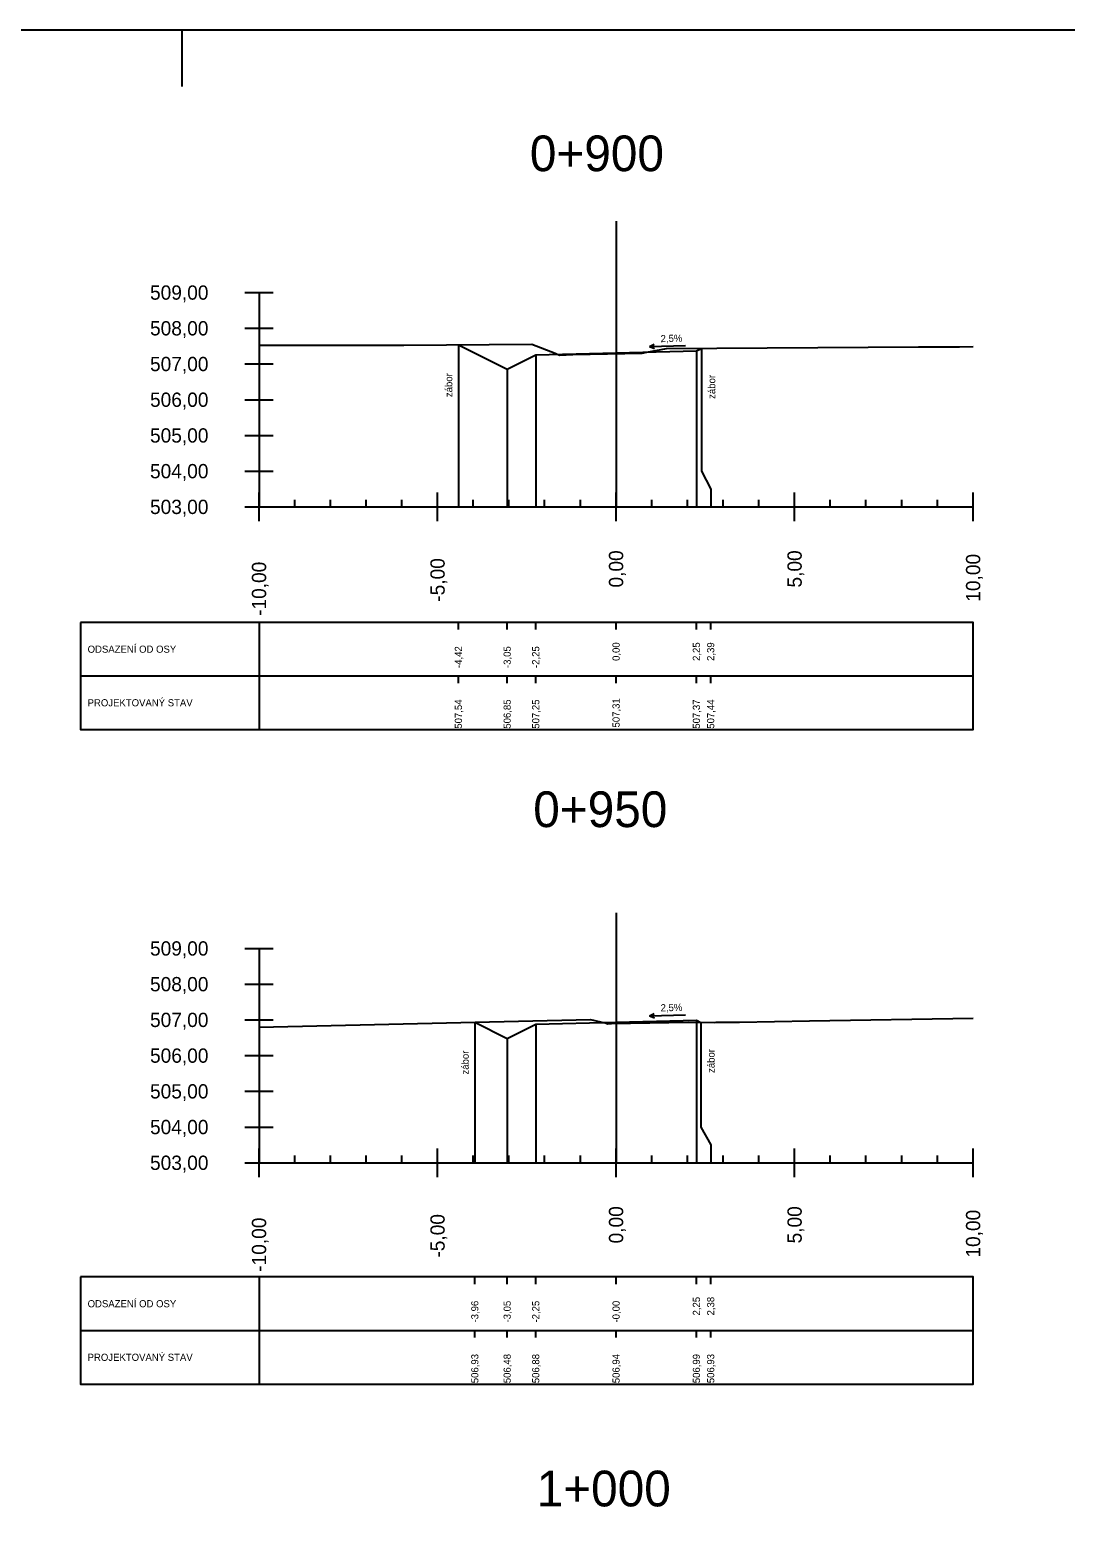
# Model space of a CAD drawing. Extents: x -631407 to -631215, y -1089700 to -1088598.
# Drawn here: x -631345.64 to -631316.63, y -1088807.44 to -1088765.23 of the extents above; entities that cross this region are included whole.
import ezdxf

# ---------------------------------------------------------------- set-up
doc = ezdxf.new("R2010")
doc.units = 0
for name, color, linetype in [('08_LEGENDA_HV', 7, 'Continuous'), ('59', 7, 'Continuous'), ('DTM-Breaklines', 7, 'Continuous'), ('NIVELETA_VYSKY', 7, 'Continuous'), ('REZ_BODY', 7, 'Continuous'), ('REZ_ODSTUPY', 7, 'Continuous'), ('REZ_POPIS', 7, 'Continuous'), ('REZ_RAMY', 7, 'Continuous'), ('REZ_STANICENI', 7, 'Continuous'), ('REZ_SVISLE', 7, 'Continuous'), ('REZ_TENKA', 7, 'Continuous'), ('REZ_TLUSTA', 7, 'Continuous'), ('TABULKA_POPIS', 7, 'Continuous'), ('TEREN', 7, 'Continuous'), ('zábor', 7, 'Continuous')]:
    doc.layers.add(name, color=color, linetype=linetype)

msp = doc.modelspace()

# ---------------------------------------------------------------- linework, layer by layer
at = {"layer": '08_LEGENDA_HV'}
msp.add_lwpolyline([(-631215.384, -1088943.435), (-631215.384, -1088765.235), (-631407.014, -1088765.235), (-631407.014, -1088943.435)], close=True, dxfattribs=at)
at = {"layer": '59'}
for p, q in [((-631339.63, -1088772.581), (-631338.83, -1088772.581)), ((-631339.23, -1088772.581), (-631339.23, -1088778.581)), ((-631339.63, -1088773.581), (-631338.83, -1088773.581)), ((-631339.63, -1088774.581), (-631338.83, -1088774.581)), ((-631339.63, -1088775.581), (-631338.83, -1088775.581)), ((-631339.63, -1088776.581), (-631338.83, -1088776.581)), ((-631339.63, -1088777.581), (-631338.83, -1088777.581)), ((-631339.63, -1088778.581), (-631338.83, -1088778.581)), ((-631339.63, -1088790.943), (-631338.83, -1088790.943)), ((-631339.23, -1088790.943), (-631339.23, -1088796.943)), ((-631339.63, -1088791.943), (-631338.83, -1088791.943)), ((-631339.63, -1088792.943), (-631338.83, -1088792.943)), ((-631339.63, -1088793.943), (-631338.83, -1088793.943)), ((-631339.63, -1088794.943), (-631338.83, -1088794.943)), ((-631339.63, -1088795.943), (-631338.83, -1088795.943)), ((-631339.63, -1088796.943), (-631338.83, -1088796.943))]:
    msp.add_line(p, q, dxfattribs=at)
at = {"layer": 'DTM-Breaklines'}
msp.add_line((-631341.384, -1088766.815), (-631341.384, -1088765.235), dxfattribs=at)
at = {"layer": 'REZ_RAMY'}
for p, q in [((-631344.23, -1088781.815), (-631344.23, -1088784.815)), ((-631339.23, -1088781.815), (-631339.23, -1088784.815)), ((-631333.646, -1088782.015), (-631333.646, -1088781.815)), ((-631332.28, -1088782.015), (-631332.28, -1088781.815)), ((-631331.48, -1088782.015), (-631331.48, -1088781.815)), ((-631329.23, -1088782.015), (-631329.23, -1088781.815)), ((-631326.98, -1088782.015), (-631326.98, -1088781.815)), ((-631326.58, -1088782.015), (-631326.58, -1088781.815)), ((-631344.23, -1088783.315), (-631319.23, -1088783.315)), ((-631333.646, -1088783.515), (-631333.646, -1088783.315)), ((-631332.28, -1088783.515), (-631332.28, -1088783.315)), ((-631331.48, -1088783.515), (-631331.48, -1088783.315)), ((-631329.23, -1088783.515), (-631329.23, -1088783.315)), ((-631326.98, -1088783.515), (-631326.98, -1088783.315)), ((-631326.58, -1088783.515), (-631326.58, -1088783.315)), ((-631344.23, -1088800.139), (-631344.23, -1088803.139)), ((-631339.23, -1088800.139), (-631339.23, -1088803.139)), ((-631333.186, -1088800.339), (-631333.186, -1088800.139)), ((-631332.28, -1088800.339), (-631332.28, -1088800.139)), ((-631331.48, -1088800.339), (-631331.48, -1088800.139)), ((-631329.23, -1088800.339), (-631329.23, -1088800.139)), ((-631326.98, -1088800.339), (-631326.98, -1088800.139)), ((-631326.58, -1088800.339), (-631326.58, -1088800.139)), ((-631344.23, -1088801.639), (-631319.23, -1088801.639)), ((-631333.186, -1088801.839), (-631333.186, -1088801.639)), ((-631332.28, -1088801.839), (-631332.28, -1088801.639)), ((-631331.48, -1088801.839), (-631331.48, -1088801.639)), ((-631329.23, -1088801.839), (-631329.23, -1088801.639)), ((-631326.98, -1088801.839), (-631326.98, -1088801.639)), ((-631326.58, -1088801.839), (-631326.58, -1088801.639))]:
    msp.add_line(p, q, dxfattribs=at)
for points in [[(-631344.23, -1088781.815), (-631344.23, -1088784.815), (-631319.23, -1088784.815), (-631319.23, -1088781.815)], [(-631344.23, -1088800.139), (-631344.23, -1088803.139), (-631319.23, -1088803.139), (-631319.23, -1088800.139)]]:
    msp.add_lwpolyline(points, close=True, dxfattribs=at)
at = {"layer": 'REZ_SVISLE'}
for points in [[(-631333.646, -1088774.044), (-631333.646, -1088777.581), (-631333.646, -1088778.081), (-631333.646, -1088778.581)], [(-631326.98, -1088774.215), (-631326.98, -1088777.581), (-631326.98, -1088778.081), (-631326.98, -1088778.581)], [(-631326.835, -1088774.143), (-631326.835, -1088777.581), (-631326.58, -1088778.081), (-631326.58, -1088778.581)], [(-631331.48, -1088774.327), (-631331.48, -1088777.581), (-631331.48, -1088778.081), (-631331.48, -1088778.581)], [(-631329.23, -1088774.271), (-631329.23, -1088777.581), (-631329.23, -1088778.081), (-631329.23, -1088778.581)], [(-631332.28, -1088774.727), (-631332.28, -1088777.581), (-631332.28, -1088778.081), (-631332.28, -1088778.581)], [(-631333.186, -1088793.009), (-631333.186, -1088795.943), (-631333.186, -1088796.443), (-631333.186, -1088796.943)], [(-631331.48, -1088793.063), (-631331.48, -1088795.943), (-631331.48, -1088796.443), (-631331.48, -1088796.943)], [(-631329.23, -1088793.006), (-631329.23, -1088795.943), (-631329.23, -1088796.443), (-631329.23, -1088796.943)], [(-631326.98, -1088792.95), (-631326.98, -1088795.943), (-631326.98, -1088796.443), (-631326.98, -1088796.943)], [(-631326.854, -1088793.013), (-631326.854, -1088795.943), (-631326.58, -1088796.443), (-631326.58, -1088796.943)], [(-631332.28, -1088793.463), (-631332.28, -1088795.943), (-631332.28, -1088796.443), (-631332.28, -1088796.943)]]:
    msp.add_lwpolyline(points, dxfattribs=at)
at = {"layer": 'REZ_TENKA'}
for p, q in [((-631338.23, -1088778.581), (-631338.23, -1088778.381)), ((-631337.23, -1088778.581), (-631337.23, -1088778.381)), ((-631336.23, -1088778.581), (-631336.23, -1088778.381)), ((-631335.23, -1088778.581), (-631335.23, -1088778.381)), ((-631333.23, -1088778.581), (-631333.23, -1088778.381)), ((-631332.23, -1088778.581), (-631332.23, -1088778.381)), ((-631331.23, -1088778.581), (-631331.23, -1088778.381)), ((-631330.23, -1088778.581), (-631330.23, -1088778.381)), ((-631328.23, -1088778.581), (-631328.23, -1088778.381)), ((-631327.23, -1088778.581), (-631327.23, -1088778.381)), ((-631326.23, -1088778.581), (-631326.23, -1088778.381)), ((-631325.23, -1088778.581), (-631325.23, -1088778.381)), ((-631323.23, -1088778.581), (-631323.23, -1088778.381)), ((-631322.23, -1088778.581), (-631322.23, -1088778.381)), ((-631321.23, -1088778.581), (-631321.23, -1088778.381)), ((-631320.23, -1088778.581), (-631320.23, -1088778.381)), ((-631338.23, -1088796.943), (-631338.23, -1088796.743)), ((-631337.23, -1088796.943), (-631337.23, -1088796.743)), ((-631336.23, -1088796.943), (-631336.23, -1088796.743)), ((-631335.23, -1088796.943), (-631335.23, -1088796.743)), ((-631333.23, -1088796.943), (-631333.23, -1088796.743)), ((-631332.23, -1088796.943), (-631332.23, -1088796.743)), ((-631331.23, -1088796.943), (-631331.23, -1088796.743)), ((-631330.23, -1088796.943), (-631330.23, -1088796.743)), ((-631328.23, -1088796.943), (-631328.23, -1088796.743)), ((-631327.23, -1088796.943), (-631327.23, -1088796.743)), ((-631326.23, -1088796.943), (-631326.23, -1088796.743)), ((-631325.23, -1088796.943), (-631325.23, -1088796.743)), ((-631323.23, -1088796.943), (-631323.23, -1088796.743)), ((-631322.23, -1088796.943), (-631322.23, -1088796.743)), ((-631321.23, -1088796.943), (-631321.23, -1088796.743)), ((-631320.23, -1088796.943), (-631320.23, -1088796.743))]:
    msp.add_line(p, q, dxfattribs=at)
at = {"layer": 'REZ_TLUSTA'}
for p, q in [((-631329.23, -1088770.581), (-631329.23, -1088778.581)), ((-631339.23, -1088778.981), (-631339.23, -1088778.181)), ((-631334.23, -1088778.981), (-631334.23, -1088778.181)), ((-631329.23, -1088778.981), (-631329.23, -1088778.181)), ((-631324.23, -1088778.981), (-631324.23, -1088778.181)), ((-631319.23, -1088778.981), (-631319.23, -1088778.181)), ((-631339.23, -1088778.581), (-631319.23, -1088778.581)), ((-631329.23, -1088789.943), (-631329.23, -1088796.943)), ((-631339.23, -1088797.343), (-631339.23, -1088796.543)), ((-631334.23, -1088797.343), (-631334.23, -1088796.543)), ((-631329.23, -1088797.343), (-631329.23, -1088796.543)), ((-631324.23, -1088797.343), (-631324.23, -1088796.543)), ((-631319.23, -1088797.343), (-631319.23, -1088796.543)), ((-631339.23, -1088796.943), (-631319.23, -1088796.943))]:
    msp.add_line(p, q, dxfattribs=at)
at = {"layer": 'TEREN'}
for points in [[(-631339.23, -1088774.057), (-631335.173, -1088774.058), (-631331.587, -1088774.026), (-631330.936, -1088774.282), (-631330.814, -1088774.33), (-631330.443, -1088774.317), (-631328.498, -1088774.278), (-631328.368, -1088774.254), (-631327.813, -1088774.149), (-631320.761, -1088774.101), (-631319.608, -1088774.098), (-631319.23, -1088774.093)], [(-631333.646, -1088774.044), (-631332.28, -1088774.727), (-631331.48, -1088774.327), (-631329.23, -1088774.271), (-631326.98, -1088774.215), (-631326.835, -1088774.143)], [(-631339.23, -1088793.149), (-631329.945, -1088792.934), (-631329.504, -1088793.034), (-631329.467, -1088793.049), (-631329.355, -1088793.044), (-631327.214, -1088793.011), (-631326.463, -1088793.015), (-631326.422, -1088793.008), (-631325.772, -1088793.007), (-631323.81, -1088792.965), (-631319.23, -1088792.892)], [(-631333.186, -1088793.009), (-631332.28, -1088793.463), (-631331.48, -1088793.063), (-631329.23, -1088793.006), (-631326.98, -1088792.95), (-631326.854, -1088793.013)]]:
    msp.add_lwpolyline(points, dxfattribs=at)
at = {"layer": 'zábor'}
for p, q in [((-631328.297, -1088774.092), (-631328.16, -1088774.027)), ((-631328.297, -1088774.092), (-631327.289, -1088774.066)), ((-631328.297, -1088774.092), (-631328.157, -1088774.149)), ((-631328.297, -1088792.827), (-631328.16, -1088792.762)), ((-631328.297, -1088792.827), (-631327.289, -1088792.802)), ((-631328.297, -1088792.827), (-631328.157, -1088792.885))]:
    msp.add_line(p, q, dxfattribs=at)

# ---------------------------------------------------------------- texts
at = {"layer": 'NIVELETA_VYSKY'}
for s, p in [('507,31', (-631329.13, -1088784.757)), ('507,54', (-631333.546, -1088784.791)), ('506,85', (-631332.18, -1088784.791)), ('507,25', (-631331.38, -1088784.791)), ('507,37', (-631326.88, -1088784.791)), ('507,44', (-631326.48, -1088784.791)), ('506,93', (-631333.086, -1088803.115)), ('506,48', (-631332.18, -1088803.115)), ('506,88', (-631331.38, -1088803.115)), ('506,94', (-631329.13, -1088803.115)), ('506,99', (-631326.88, -1088803.115)), ('506,93', (-631326.48, -1088803.115))]:
    msp.add_text(s, height=0.2, rotation=90, dxfattribs=at).set_placement(p)
at = {"layer": 'REZ_BODY'}
for s, p in [('-4,42', (-631333.546, -1088783.092)), ('-3,05', (-631332.18, -1088783.092)), ('-2,25', (-631331.38, -1088783.092)), ('0,00', (-631329.13, -1088782.894)), ('2,25', (-631326.88, -1088782.894)), ('2,39', (-631326.48, -1088782.894)), ('-3,96', (-631333.086, -1088801.416)), ('-3,05', (-631332.18, -1088801.416)), ('-2,25', (-631331.38, -1088801.416)), ('-0,00', (-631329.13, -1088801.416)), ('2,25', (-631326.88, -1088801.218)), ('2,38', (-631326.48, -1088801.218))]:
    msp.add_text(s, height=0.2, rotation=90, dxfattribs=at).set_placement(p)
at = {"layer": 'REZ_ODSTUPY'}
for s, p in [('-10,00', (-631339.03, -1088781.633)), ('-5,00', (-631334.03, -1088781.236)), ('0,00', (-631329.03, -1088780.839)), ('5,00', (-631324.03, -1088780.839)), ('10,00', (-631319.03, -1088781.236)), ('0,00', (-631329.03, -1088799.201)), ('5,00', (-631324.03, -1088799.201)), ('10,00', (-631319.03, -1088799.598)), ('-10,00', (-631339.03, -1088799.995)), ('-5,00', (-631334.03, -1088799.598))]:
    msp.add_text(s, height=0.4, rotation=90, dxfattribs=at).set_placement(p)
at = {"layer": 'REZ_POPIS'}
for s, p in [('509,00', (-631342.282, -1088772.781)), ('508,00', (-631342.282, -1088773.781)), ('507,00', (-631342.282, -1088774.781)), ('506,00', (-631342.282, -1088775.781)), ('505,00', (-631342.282, -1088776.781)), ('504,00', (-631342.282, -1088777.781)), ('503,00', (-631342.282, -1088778.781)), ('509,00', (-631342.282, -1088791.143)), ('508,00', (-631342.282, -1088792.143)), ('507,00', (-631342.282, -1088793.143)), ('506,00', (-631342.282, -1088794.143)), ('505,00', (-631342.282, -1088795.143)), ('504,00', (-631342.282, -1088796.143)), ('503,00', (-631342.282, -1088797.143))]:
    msp.add_text(s, height=0.4, dxfattribs=at).set_placement(p)
at = {"layer": 'REZ_STANICENI'}
for s, p in [('0+900', (-631331.644, -1088769.184)), ('0+950', (-631331.549, -1088787.546)), ('1+000', (-631331.453, -1088806.563))]:
    msp.add_text(s, height=1, dxfattribs=at).set_placement(p)
at = {"layer": 'TABULKA_POPIS'}
for s, p in [('ODSAZENÍ OD OSY', (-631344.03, -1088782.665)), ('PROJEKTOVANÝ STAV', (-631344.03, -1088784.165)), ('ODSAZENÍ OD OSY', (-631344.03, -1088800.989)), ('PROJEKTOVANÝ STAV', (-631344.03, -1088802.489))]:
    msp.add_text(s, height=0.2, dxfattribs=at).set_placement(p)
at = {"layer": 'zábor'}
for s, rotation, p in [('2,5%', 1.4321, (-631327.98, -1088773.971)), ('zábor', 90, (-631333.816, -1088775.508)), ('zábor', 90, (-631326.452, -1088775.557)), ('2,5%', 1.4321, (-631327.98, -1088792.706)), ('zábor', 90, (-631333.356, -1088794.473)), ('zábor', 90, (-631326.471, -1088794.428))]:
    msp.add_text(s, height=0.2, rotation=rotation, dxfattribs=at).set_placement(p)

doc.saveas('drawing.dxf')
